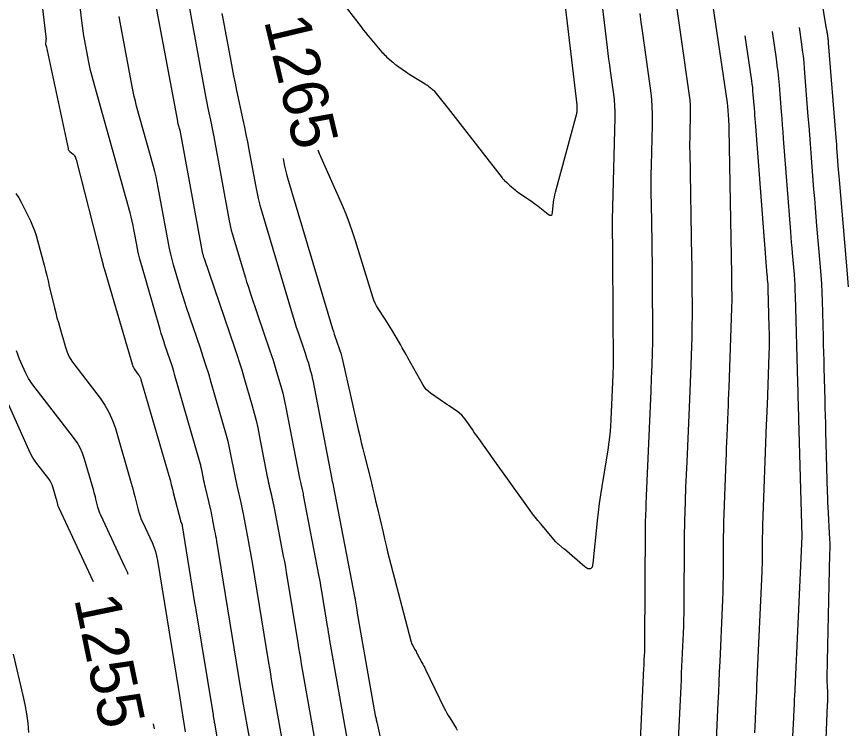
# Model space of a CAD drawing. Extents: x 658976 to 668726, y 639543 to 647196.
# Drawn here: x 661669.8 to 661779.9, y 642153.2 to 642247.3 of the extents above; entities that cross this region are included whole.
import ezdxf

# ---------------------------------------------------------------- set-up
doc = ezdxf.new("R2010")
doc.units = 0
for name, color, linetype in [('Ex_Contour Labels', 7, 'Continuous'), ('Ex_Major Contours', 7, 'Continuous'), ('Ex_Minor Contours', 7, 'Continuous')]:
    doc.layers.add(name, color=color, linetype=linetype)

msp = doc.modelspace()

# ---------------------------------------------------------------- linework, layer by layer
at = {"layer": 'Ex_Major Contours'}
for points in [[(661746.77, 642253.54), (661748, 642243.22), (661748.09, 642242.45), (661748.19, 642241.69), (661748.29, 642240.92), (661748.4, 642240.15), (661748.83, 642237.08), (661748.92, 642236.31), (661748.98, 642235.54), (661749.01, 642234.77), (661749.01, 642234), (661748.67, 642220.45), (661748.66, 642220.03), (661748.66, 642219.6), (661748.66, 642219.17), (661748.66, 642218.75), (661748.69, 642217.04), (661748.7, 642216.61), (661748.71, 642216.19), (661748.71, 642215.76), (661748.71, 642215.33), (661748.78, 642201.24), (661748.78, 642201.13), (661748.78, 642201.02), (661748.78, 642200.91), (661748.78, 642200.8), (661748.76, 642200.36), (661748.76, 642200.26), (661748.75, 642200.15), (661748.75, 642200.04), (661748.75, 642199.93), (661748.49, 642194.05), (661748.43, 642193.04), (661748.34, 642192.03), (661748.22, 642191.02), (661748.07, 642190.02), (661747.27, 642185.18), (661747.09, 642184.05), (661746.93, 642182.91), (661746.79, 642181.76), (661746.66, 642180.62), (661746.1, 642174.99), (661745.99, 642174.49), (661745.77, 642174.26), (661745.45, 642174.28), (661745.02, 642174.56), (661742.33, 642176.86), (661742.24, 642176.93), (661742.16, 642177), (661742.07, 642177.07), (661741.99, 642177.14), (661741.53, 642177.53), (661741.51, 642177.55), (661741.48, 642177.57), (661741.45, 642177.6), (661741.43, 642177.62), (661741.32, 642177.72), (661741.29, 642177.75), (661741.27, 642177.78), (661741.24, 642177.8), (661741.22, 642177.83), (661739.15, 642180.27), (661738.8, 642180.69), (661738.47, 642181.12), (661738.13, 642181.55), (661737.81, 642181.99), (661732.7, 642189.12), (661732.49, 642189.42), (661732.28, 642189.72), (661732.06, 642190.02), (661731.85, 642190.32), (661731, 642191.51), (661730.78, 642191.81), (661730.57, 642192.11), (661730.36, 642192.41), (661730.15, 642192.71), (661729.2, 642194.07), (661728.99, 642194.35), (661728.75, 642194.6), (661728.5, 642194.83), (661728.22, 642195.04), (661727.06, 642195.82), (661726.77, 642196.02), (661726.48, 642196.22), (661726.19, 642196.42), (661725.91, 642196.62), (661724.6, 642197.53), (661724.3, 642197.76), (661724.03, 642198.02), (661723.8, 642198.32), (661723.6, 642198.64), (661721.63, 642202.18), (661721.38, 642202.62), (661721.13, 642203.07), (661720.87, 642203.51), (661720.62, 642203.95), (661719.49, 642205.87), (661719.27, 642206.23), (661719.05, 642206.59), (661718.83, 642206.95), (661718.6, 642207.3), (661717.69, 642208.7), (661717.47, 642209.06), (661717.28, 642209.42), (661717.12, 642209.81), (661716.98, 642210.2), (661714.7, 642217.66), (661714.31, 642218.84), (661713.89, 642220.02), (661713.44, 642221.18), (661712.95, 642222.33), (661710.15, 642228.67), (661710.04, 642228.92), (661709.93, 642229.18), (661709.83, 642229.43), (661709.74, 642229.65)], [(661705.42, 642149.22), (661703.72, 642158.88), (661703.59, 642159.62), (661703.47, 642160.37), (661703.34, 642161.12), (661703.22, 642161.86), (661701.05, 642175.1), (661700.93, 642175.83), (661700.8, 642176.56), (661700.67, 642177.29), (661700.53, 642178.02), (661699.85, 642181.55), (661699.77, 642181.97), (661699.68, 642182.39), (661699.59, 642182.81), (661699.5, 642183.22), (661699.1, 642184.89), (661699.01, 642185.3), (661698.92, 642185.72), (661698.83, 642186.14), (661698.75, 642186.56), (661698.15, 642189.64), (661698.02, 642190.3), (661697.87, 642190.95), (661697.71, 642191.59), (661697.53, 642192.23), (661695.59, 642198.92), (661695.26, 642200.06), (661694.9, 642201.2), (661694.54, 642202.34), (661694.16, 642203.47), (661692.32, 642208.84), (661692.08, 642209.54), (661691.86, 642210.24), (661691.64, 642210.94), (661691.43, 642211.65), (661690.61, 642214.49), (661690.42, 642215.2), (661690.24, 642215.91), (661690.08, 642216.63), (661689.94, 642217.35), (661688.59, 642224.73), (661688.45, 642225.43), (661688.3, 642226.12), (661688.13, 642226.82), (661687.95, 642227.5), (661685.72, 642235.47), (661685.55, 642236.12), (661685.4, 642236.76), (661685.25, 642237.42), (661685.12, 642238.07), (661683.67, 642245.89), (661683.54, 642246.61), (661683.42, 642247.34)], [(661769.81, 642245.34), (661770.34, 642241.75), (661770.46, 642240.87), (661770.57, 642240), (661770.66, 642239.12), (661770.74, 642238.25), (661771.02, 642234.73), (661771.09, 642233.85), (661771.16, 642232.97), (661771.22, 642232.1), (661771.29, 642231.22), (661772.24, 642218.85), (661772.3, 642218.14), (661772.35, 642217.44), (661772.41, 642216.73), (661772.47, 642216.03), (661772.72, 642213.21), (661772.77, 642212.5), (661772.82, 642211.8), (661772.85, 642211.09), (661772.88, 642210.38), (661773.19, 642198.92), (661773.2, 642198.51), (661773.21, 642198.11), (661773.22, 642197.7), (661773.23, 642197.3), (661773.27, 642195.68), (661773.29, 642195.28), (661773.3, 642194.87), (661773.31, 642194.47), (661773.32, 642194.06), (661773.74, 642178.6), (661773.74, 642178.59), (661773.74, 642178.57), (661773.74, 642178.56), (661772.78, 642157.37), (661772.76, 642157.14), (661772.75, 642156.91), (661772.74, 642156.68), (661772.73, 642156.45), (661772.69, 642155.54), (661772.68, 642155.31), (661772.67, 642155.08), (661772.65, 642154.85), (661772.64, 642154.62), (661771.77, 642138.06)], [(661680.03, 642172.56), (661675.42, 642182.39), (661675.38, 642182.48), (661675.35, 642182.58), (661675.31, 642182.67), (661675.29, 642182.77), (661675.19, 642183.17), (661675.16, 642183.27), (661675.14, 642183.37), (661675.11, 642183.47), (661675.08, 642183.57), (661674.63, 642185.11), (661674.53, 642185.4), (661674.41, 642185.67), (661674.27, 642185.93), (661674.09, 642186.18), (661672.53, 642188.21), (661672.22, 642188.63), (661671.94, 642189.07), (661671.69, 642189.53), (661671.46, 642190), (661667.08, 642199.71)], [(661669.4, 642162.97), (661670.65, 642157.54), (661670.91, 642156.31), (661671.13, 642155.09), (661671.3, 642153.85), (661671.43, 642152.61)]]:
    msp.add_lwpolyline(points, dxfattribs=at)
at = {"layer": 'Ex_Minor Contours'}
for points in [[(661672.02, 642259), (661673.71, 642244.67), (661673.72, 642244.56), (661673.73, 642244.45), (661673.73, 642244.34), (661673.72, 642244.24), (661673.68, 642243.62), (661673.68, 642243.61), (661673.68, 642243.59), (661673.68, 642243.58), (661673.69, 642243.56), (661673.71, 642243.51), (661673.72, 642243.49), (661673.72, 642243.48), (661673.73, 642243.46), (661673.73, 642243.45), (661676.64, 642229.86), (661676.68, 642229.75), (661676.72, 642229.66), (661676.79, 642229.57), (661676.87, 642229.49), (661677.31, 642229.14), (661677.36, 642229.1), (661677.41, 642229.04), (661677.45, 642228.99), (661677.48, 642228.93), (661677.61, 642228.67), (661677.64, 642228.61), (661677.66, 642228.55), (661677.68, 642228.48), (661677.7, 642228.41), (661681.04, 642215.45), (661681.07, 642215.33), (661681.1, 642215.21), (661681.13, 642215.09), (661681.16, 642214.97), (661681.28, 642214.48), (661681.31, 642214.36), (661681.34, 642214.24), (661681.37, 642214.11), (661681.41, 642213.99), (661685.16, 642201.24), (661685.22, 642201.06), (661685.29, 642200.89), (661685.38, 642200.74), (661685.49, 642200.58), (661685.94, 642199.99), (661686.05, 642199.84), (661686.14, 642199.68), (661686.22, 642199.51), (661686.27, 642199.34), (661689.96, 642186.63), (661690.14, 642186.03), (661690.3, 642185.42), (661690.47, 642184.81), (661690.62, 642184.2), (661691.51, 642180.66), (661691.52, 642180.6), (661691.54, 642180.54), (661691.56, 642180.49), (661691.59, 642180.43), (661691.69, 642180.21), (661691.71, 642180.16), (661691.73, 642180.1), (661691.75, 642180.04), (661691.76, 642179.98), (661693.4, 642169.79), (661693.44, 642169.56), (661693.48, 642169.33), (661693.52, 642169.1), (661693.55, 642168.87), (661695.83, 642154.96), (661695.84, 642154.91), (661695.85, 642154.86), (661695.86, 642154.81), (661695.86, 642154.77), (661695.98, 642154.13), (661695.99, 642154.08), (661696, 642154.02), (661696, 642153.96), (661696.01, 642153.91), (661699.4, 642133.43)], [(661762.41, 642150.69), (661762.69, 642156.59), (661762.75, 642157.95), (661762.82, 642159.3), (661762.88, 642160.65), (661762.94, 642162), (661763.27, 642169.15), (661763.31, 642170.19), (661763.34, 642171.22), (661763.36, 642172.25), (661763.37, 642173.29), (661763.39, 642177.42), (661763.4, 642178.45), (661763.42, 642179.48), (661763.45, 642180.52), (661763.48, 642181.55), (661763.74, 642188.66), (661763.77, 642189.46), (661763.8, 642190.26), (661763.83, 642191.06), (661763.87, 642191.86), (661764.01, 642195.06), (661764.04, 642195.86), (661764.07, 642196.65), (661764.1, 642197.45), (661764.13, 642198.25), (661764.5, 642208.77), (661764.51, 642209.14), (661764.52, 642209.51), (661764.52, 642209.88), (661764.52, 642210.25), (661764.51, 642211.73), (661764.51, 642212.1), (661764.51, 642212.47), (661764.5, 642212.84), (661764.5, 642213.21), (661764.15, 642232.47), (661764.14, 642232.78), (661764.13, 642233.09), (661764.11, 642233.4), (661764.09, 642233.71), (661763.95, 642235.48), (661763.95, 642235.56), (661763.94, 642235.63), (661763.93, 642235.78), (661763.93, 642235.81), (661763.92, 642235.85), (661763.92, 642235.89), (661763.91, 642235.92), (661760.67, 642257.95)], [(661700.7, 642151.68), (661699.79, 642156.82), (661699.73, 642157.22), (661699.66, 642157.62), (661699.59, 642158.01), (661699.52, 642158.41), (661696.33, 642177.93), (661696.27, 642178.28), (661696.21, 642178.62), (661696.15, 642178.97), (661696.08, 642179.31), (661695.82, 642180.69), (661695.75, 642181.03), (661695.68, 642181.37), (661695.61, 642181.72), (661695.53, 642182.06), (661694.82, 642185.04), (661694.76, 642185.33), (661694.69, 642185.62), (661694.63, 642185.92), (661694.57, 642186.21), (661694.34, 642187.39), (661694.28, 642187.69), (661694.22, 642187.98), (661694.14, 642188.27), (661694.06, 642188.56), (661690.79, 642199.85), (661690.64, 642200.36), (661690.49, 642200.87), (661690.32, 642201.38), (661690.15, 642201.88), (661689.47, 642203.89), (661689.3, 642204.4), (661689.13, 642204.9), (661688.98, 642205.41), (661688.83, 642205.92), (661686.3, 642214.67), (661686.14, 642215.22), (661686.01, 642215.78), (661685.88, 642216.34), (661685.77, 642216.9), (661685.36, 642219.15), (661685.25, 642219.71), (661685.13, 642220.27), (661684.99, 642220.83), (661684.85, 642221.38), (661679.95, 642238.91), (661679.78, 642239.56), (661679.62, 642240.21), (661679.48, 642240.86), (661679.35, 642241.51), (661678.86, 642244.14), (661678.75, 642244.8), (661678.64, 642245.45), (661678.55, 642246.12), (661678.46, 642246.78), (661677.5, 642255)], [(661757.18, 642146.29), (661757.77, 642158.73), (661757.81, 642159.61), (661757.85, 642160.49), (661757.89, 642161.37), (661757.93, 642162.25), (661758.09, 642165.78), (661758.13, 642166.67), (661758.15, 642167.55), (661758.17, 642168.43), (661758.18, 642169.31), (661758.23, 642178.24), (661758.24, 642179.09), (661758.25, 642179.94), (661758.27, 642180.79), (661758.3, 642181.64), (661758.42, 642185.04), (661758.45, 642185.89), (661758.49, 642186.74), (661758.52, 642187.59), (661758.56, 642188.44), (661758.87, 642195.6), (661758.92, 642196.71), (661758.96, 642197.82), (661759.01, 642198.93), (661759.05, 642200.03), (661759.22, 642204.92), (661759.24, 642205.8), (661759.26, 642206.68), (661759.27, 642207.56), (661759.27, 642208.44), (661759.25, 642211.95), (661759.25, 642212.83), (661759.24, 642213.71), (661759.23, 642214.59), (661759.21, 642215.46), (661758.96, 642229.38), (661758.95, 642230.01), (661758.95, 642230.63), (661758.96, 642231.26), (661758.97, 642231.88), (661759.03, 642234.38), (661759.03, 642235.01), (661759.01, 642235.63), (661758.96, 642236.25), (661758.89, 642236.87), (661756.64, 642252.75)], [(661779.93, 642211.6), (661779.9, 642212.16), (661779.86, 642212.72), (661779.82, 642213.28), (661778.73, 642225.72), (661778.69, 642226.19), (661778.66, 642226.66), (661778.62, 642227.12), (661778.58, 642227.59), (661778.44, 642229.46), (661778.4, 642229.93), (661778.37, 642230.39), (661778.33, 642230.86), (661778.29, 642231.33), (661777.3, 642243.85), (661777.29, 642244), (661777.27, 642244.16), (661777.25, 642244.31), (661777.23, 642244.46), (661777.14, 642245.08), (661777.12, 642245.23), (661777.09, 642245.39), (661777.07, 642245.54), (661777.04, 642245.69), (661775.92, 642252.5)], [(661712.58, 642249.74), (661715.43, 642245.96), (661715.72, 642245.58), (661716.02, 642245.21), (661716.32, 642244.84), (661716.62, 642244.47), (661718.19, 642242.63), (661718.33, 642242.47), (661718.48, 642242.31), (661718.64, 642242.16), (661718.8, 642242.01), (661719.44, 642241.43), (661719.61, 642241.29), (661719.78, 642241.15), (661719.95, 642241.01), (661720.12, 642240.89), (661721.15, 642240.16), (661721.39, 642240), (661721.62, 642239.84), (661721.86, 642239.68), (661722.1, 642239.53), (661723.9, 642238.43), (661724.01, 642238.35), (661724.13, 642238.28), (661724.24, 642238.2), (661724.35, 642238.11), (661724.78, 642237.77), (661724.89, 642237.69), (661724.99, 642237.59), (661725.08, 642237.49), (661725.17, 642237.39), (661726.93, 642235.19), (661727.25, 642234.79), (661727.57, 642234.38), (661727.89, 642233.98), (661728.2, 642233.57), (661734.08, 642226.02), (661734.15, 642225.93), (661734.22, 642225.84), (661734.3, 642225.76), (661734.38, 642225.68), (661734.72, 642225.36), (661734.8, 642225.28), (661734.89, 642225.2), (661734.97, 642225.13), (661735.06, 642225.05), (661735.8, 642224.41), (661735.95, 642224.28), (661736.11, 642224.16), (661736.27, 642224.04), (661736.43, 642223.92), (661737.97, 642222.89), (661738.26, 642222.69), (661738.54, 642222.49), (661738.81, 642222.28), (661739.08, 642222.07), (661740.17, 642221.19), (661740.4, 642221.05), (661740.58, 642221.04), (661740.7, 642221.17), (661740.76, 642221.43), (661740.9, 642222.77), (661740.95, 642223.11), (661741, 642223.44), (661741.07, 642223.77), (661741.15, 642224.09), (661743.97, 642234.52), (661743.99, 642234.61), (661744.01, 642234.71), (661744.02, 642234.81), (661744.03, 642234.91), (661744.04, 642235.47), (661744.04, 642235.49), (661744.04, 642235.51), (661744.04, 642235.52), (661744.04, 642235.54), (661744.03, 642235.61), (661744.02, 642235.62), (661744.02, 642235.64), (661744.02, 642235.66), (661744.02, 642235.67), (661742.11, 642251.71)], [(661688.22, 642248.99), (661691.11, 642233.48), (661691.12, 642233.4), (661691.14, 642233.32), (661691.16, 642233.24), (661691.18, 642233.15), (661691.46, 642232.16), (661691.48, 642232.07), (661691.5, 642231.99), (661691.52, 642231.9), (661691.54, 642231.81), (661694.41, 642216.15), (661694.42, 642216.09), (661694.43, 642216.03), (661694.44, 642215.97), (661694.46, 642215.92), (661694.53, 642215.69), (661694.54, 642215.63), (661694.56, 642215.57), (661694.58, 642215.51), (661694.6, 642215.46), (661698.72, 642203.42), (661699.03, 642202.48), (661699.34, 642201.54), (661699.63, 642200.59), (661699.91, 642199.64), (661701.02, 642195.83), (661701.28, 642194.87), (661701.52, 642193.91), (661701.75, 642192.94), (661701.94, 642191.97), (661703.01, 642186.43), (661703.07, 642186.12), (661703.14, 642185.82), (661703.2, 642185.52), (661703.27, 642185.21), (661703.56, 642184.01), (661703.63, 642183.71), (661703.69, 642183.4), (661703.76, 642183.1), (661703.82, 642182.8), (661705.13, 642175.95), (661705.27, 642175.23), (661705.4, 642174.5), (661705.52, 642173.78), (661705.64, 642173.05), (661707.04, 642164.51), (661707.16, 642163.82), (661707.27, 642163.12), (661707.39, 642162.43), (661707.51, 642161.73), (661710.27, 642146.07)], [(661692.71, 642248.38), (661694.82, 642236.8), (661694.91, 642236.35), (661695, 642235.9), (661695.09, 642235.45), (661695.18, 642235), (661695.57, 642233.21), (661695.67, 642232.76), (661695.76, 642232.31), (661695.85, 642231.86), (661695.93, 642231.41), (661697.96, 642220.32), (661698.05, 642219.9), (661698.14, 642219.48), (661698.25, 642219.06), (661698.36, 642218.65), (661700.11, 642212.78), (661700.28, 642212.22), (661700.46, 642211.66), (661700.64, 642211.1), (661700.83, 642210.54), (661703.37, 642203.11), (661703.58, 642202.49), (661703.78, 642201.87), (661703.97, 642201.25), (661704.15, 642200.63), (661704.88, 642198.14), (661705.05, 642197.51), (661705.21, 642196.88), (661705.35, 642196.25), (661705.48, 642195.61), (661707.28, 642186.29), (661707.32, 642186.1), (661707.36, 642185.92), (661707.4, 642185.73), (661707.44, 642185.54), (661707.62, 642184.79), (661707.66, 642184.61), (661707.7, 642184.42), (661707.74, 642184.23), (661707.78, 642184.04), (661709.84, 642173.28), (661709.92, 642172.86), (661710, 642172.44), (661710.07, 642172.02), (661710.14, 642171.6), (661710.95, 642166.68), (661711.01, 642166.28), (661711.08, 642165.87), (661711.15, 642165.47), (661711.22, 642165.07), (661715.34, 642141.67)], [(661697.01, 642247.75), (661697.18, 642246.85), (661698.17, 642241.44), (661698.35, 642240.47), (661698.54, 642239.49), (661698.74, 642238.52), (661698.94, 642237.55), (661699.78, 642233.66), (661699.99, 642232.69), (661700.19, 642231.71), (661700.38, 642230.74), (661700.56, 642229.76), (661701.43, 642225.01), (661701.61, 642224.13), (661701.8, 642223.25), (661702.03, 642222.38), (661702.27, 642221.51), (661706.3, 642208), (661706.47, 642207.42), (661706.66, 642206.84), (661706.84, 642206.26), (661707.04, 642205.68), (661708.03, 642202.8), (661708.12, 642202.5), (661708.22, 642202.21), (661708.31, 642201.92), (661708.4, 642201.62), (661708.74, 642200.44), (661708.82, 642200.15), (661708.89, 642199.85), (661708.96, 642199.55), (661709.02, 642199.25), (661711.55, 642186.16), (661711.56, 642186.08), (661711.57, 642186.01), (661711.59, 642185.94), (661711.61, 642185.87), (661711.68, 642185.58), (661711.69, 642185.51), (661711.71, 642185.43), (661711.72, 642185.36), (661711.74, 642185.29), (661714.55, 642170.61), (661714.58, 642170.49), (661714.6, 642170.38), (661714.62, 642170.27), (661714.63, 642170.16), (661714.85, 642168.84), (661714.87, 642168.73), (661714.89, 642168.63), (661714.9, 642168.52), (661714.92, 642168.41), (661717.3, 642154.89), (661717.31, 642154.84), (661717.32, 642154.79), (661717.33, 642154.74), (661717.35, 642154.69), (661717.4, 642154.48), (661717.41, 642154.44), (661717.42, 642154.4), (661717.42, 642154.36), (661717.43, 642154.32), (661717.46, 642154.17), (661717.47, 642154.13), (661717.48, 642154.09), (661717.49, 642154.05), (661717.49, 642154.01), (661719.69, 642144.19)], [(661751.95, 642141.94), (661752.86, 642161.13), (661752.87, 642161.41), (661752.88, 642161.68), (661752.9, 642161.96), (661752.91, 642162.23), (661752.96, 642163.33), (661752.97, 642163.6), (661752.98, 642163.88), (661752.98, 642164.15), (661752.99, 642164.42), (661753.07, 642179.7), (661753.07, 642180.05), (661753.08, 642180.4), (661753.08, 642180.75), (661753.1, 642181.1), (661753.15, 642182.51), (661753.16, 642182.86), (661753.17, 642183.21), (661753.19, 642183.57), (661753.2, 642183.92), (661753.81, 642197.77), (661753.83, 642198.37), (661753.86, 642198.98), (661753.88, 642199.59), (661753.9, 642200.2), (661753.99, 642202.63), (661754.01, 642203.24), (661754.02, 642203.85), (661754.03, 642204.46), (661754.03, 642205.07), (661753.99, 642212.4), (661753.98, 642213.68), (661753.97, 642214.95), (661753.95, 642216.22), (661753.93, 642217.49), (661753.84, 642222.57), (661753.82, 642223.84), (661753.82, 642225.12), (661753.83, 642226.39), (661753.86, 642227.66), (661753.99, 642232.97), (661754, 642234.28), (661753.95, 642235.58), (661753.84, 642236.89), (661753.69, 642238.18), (661752.66, 642245.45), (661752.5, 642246.59), (661752.35, 642247.73)], [(661773.38, 642245.89), (661773.7, 642243.7), (661773.81, 642242.89), (661773.91, 642242.08), (661774, 642241.26), (661774.07, 642240.45), (661774.57, 642234.09), (661774.67, 642232.89), (661774.76, 642231.68), (661774.85, 642230.48), (661774.95, 642229.27), (661775.32, 642224.46), (661775.41, 642223.25), (661775.51, 642222.05), (661775.61, 642220.84), (661775.71, 642219.64), (661776.18, 642214.24), (661776.27, 642213.11), (661776.34, 642211.98), (661776.4, 642210.84), (661776.44, 642209.71), (661776.57, 642204.97), (661776.6, 642203.93), (661776.62, 642202.89), (661776.65, 642201.85), (661776.68, 642200.81), (661776.79, 642196.64), (661776.82, 642195.6), (661776.84, 642194.56), (661776.87, 642193.52), (661776.9, 642192.48), (661777.12, 642184.43), (661777.14, 642183.74), (661777.17, 642183.06), (661777.2, 642182.37), (661777.23, 642181.69), (661777.39, 642178.96), (661777.42, 642178.28), (661777.44, 642177.59), (661777.44, 642176.91), (661777.43, 642176.23), (661777.08, 642160), (661777.07, 642159.73), (661777.08, 642159.46), (661777.08, 642159.2), (661777.09, 642158.93), (661777.16, 642157.75), (661777.16, 642157.54), (661777.17, 642157.33), (661777.16, 642157.12), (661777.15, 642156.9), (661777.1, 642156.06), (661777.09, 642155.85), (661777.08, 642155.64), (661777.07, 642155.43), (661777.06, 642155.22), (661776.41, 642137.91)], [(661767.52, 642152.57), (661767.56, 642153.36), (661767.71, 642156.52), (661767.75, 642157.31), (661767.79, 642158.11), (661767.82, 642158.9), (661767.86, 642159.69), (661768.5, 642173.86), (661768.52, 642174.37), (661768.54, 642174.89), (661768.55, 642175.41), (661768.55, 642175.92), (661768.57, 642177.99), (661768.57, 642178.51), (661768.58, 642179.03), (661768.59, 642179.54), (661768.61, 642180.06), (661769.09, 642193.36), (661769.1, 642193.57), (661769.11, 642193.79), (661769.12, 642194), (661769.13, 642194.21), (661769.16, 642195.06), (661769.17, 642195.28), (661769.18, 642195.49), (661769.19, 642195.7), (661769.2, 642195.92), (661769.43, 642202.69), (661769.46, 642203.58), (661769.47, 642204.48), (661769.46, 642205.37), (661769.45, 642206.26), (661769.31, 642211.31), (661769.31, 642211.46), (661769.3, 642211.62), (661769.29, 642211.77), (661769.28, 642211.92), (661769.22, 642212.53), (661769.21, 642212.68), (661769.2, 642212.83), (661769.19, 642212.98), (661769.17, 642213.13), (661767.62, 642233.35), (661767.59, 642233.81), (661767.55, 642234.27), (661767.52, 642234.72), (661767.48, 642235.18), (661767.33, 642237.01), (661767.29, 642237.47), (661767.25, 642237.93), (661767.19, 642238.38), (661767.13, 642238.84), (661766.25, 642244.78)], [(661705.11, 642228.55), (661705.21, 642228.03), (661705.31, 642227.52), (661705.42, 642227.01), (661705.55, 642226.5), (661705.7, 642226), (661711.65, 642206.02), (661711.76, 642205.66), (661711.87, 642205.3), (661711.99, 642204.94), (661712.11, 642204.59), (661712.61, 642203.17), (661712.73, 642202.81), (661712.84, 642202.45), (661712.94, 642202.09), (661713.03, 642201.72), (661715.05, 642192.73), (661715.25, 642191.87), (661715.45, 642191.01), (661715.66, 642190.15), (661715.87, 642189.29), (661716.74, 642185.81), (661716.94, 642184.97), (661717.15, 642184.13), (661717.35, 642183.29), (661717.55, 642182.45), (661718.33, 642179.07), (661718.53, 642178.23), (661718.73, 642177.38), (661718.94, 642176.54), (661719.16, 642175.7), (661721.99, 642164.77), (661722.04, 642164.61), (661722.09, 642164.46), (661722.16, 642164.32), (661722.23, 642164.17), (661722.54, 642163.61), (661722.62, 642163.47), (661722.7, 642163.33), (661722.78, 642163.18), (661722.86, 642163.04), (661723.48, 642161.9), (661723.61, 642161.66), (661723.73, 642161.42), (661723.85, 642161.18), (661723.97, 642160.94), (661726.44, 642155.85), (661726.6, 642155.52), (661726.78, 642155.2), (661726.96, 642154.87), (661727.15, 642154.56), (661727.99, 642153.18), (661728.16, 642152.94)], [(661669.73, 642223.91), (661670.12, 642223.36), (661670.45, 642222.77), (661671.67, 642220.29), (661671.96, 642219.67), (661672.21, 642219.03), (661672.43, 642218.39), (661672.62, 642217.73), (661673.47, 642214.44), (661673.64, 642213.75), (661673.82, 642213.06), (661673.99, 642212.36), (661674.16, 642211.67), (661674.85, 642208.82), (661675.01, 642208.16), (661675.18, 642207.5), (661675.36, 642206.84), (661675.55, 642206.19), (661676.31, 642203.58), (661676.53, 642202.94), (661676.81, 642202.33), (661677.14, 642201.75), (661677.53, 642201.2), (661680.88, 642196.84), (661681.52, 642195.91), (661682.08, 642194.93), (661682.54, 642193.91), (661682.91, 642192.83), (661685, 642185.61), (661685.13, 642185.17), (661685.25, 642184.74), (661685.36, 642184.3), (661685.48, 642183.86), (661685.92, 642182.1), (661686.04, 642181.66), (661686.18, 642181.23), (661686.34, 642180.81), (661686.52, 642180.4), (661687.76, 642177.76), (661688, 642177.18), (661688.21, 642176.59), (661688.37, 642175.98), (661688.5, 642175.36), (661691.25, 642158.33), (661691.34, 642157.77), (661691.43, 642157.21), (661691.52, 642156.64), (661691.61, 642156.08), (661691.97, 642153.84), (661692.06, 642153.28), (661692.15, 642152.72)], [(661684.6, 642173.51), (661684.49, 642173.82), (661684.18, 642174.54), (661680.97, 642181.39), (661680.86, 642181.65), (661680.76, 642181.9), (661680.68, 642182.17), (661680.6, 642182.44), (661680.33, 642183.51), (661680.26, 642183.78), (661680.19, 642184.05), (661680.12, 642184.32), (661680.04, 642184.59), (661678.82, 642188.79), (661678.56, 642189.56), (661678.23, 642190.29), (661677.83, 642191), (661677.36, 642191.66), (661671.87, 642198.81), (661671.64, 642199.13), (661671.43, 642199.46), (661671.23, 642199.81), (661671.06, 642200.17), (661670.4, 642201.63), (661670.24, 642201.99), (661670.09, 642202.36), (661669.95, 642202.74), (661669.83, 642203.11)], [(661688.07, 642153.1), (661687.97, 642153.78)]]:
    msp.add_lwpolyline(points, dxfattribs=at)

# ---------------------------------------------------------------- texts
at = {"layer": 'Ex_Contour Labels'}
for s, rotation, p in [('1265', 283.4214, (661702.56, 642246.79)), ('1255', 281.6747, (661677.44, 642170.32))]:
    msp.add_text(s, height=6, rotation=rotation, dxfattribs=at).set_placement(p)

doc.saveas('drawing.dxf')
